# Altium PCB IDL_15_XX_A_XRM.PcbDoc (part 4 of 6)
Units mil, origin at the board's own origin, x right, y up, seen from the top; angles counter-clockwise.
Board outline 6653.34 x 6653.34 mil, 6 copper layers (Top Layer - SIG1, Layer 2 - GND1, Layer 3 - PWR, Layer 4 - PWR, Layer 5 - GND2, Bottom Layer - SIG4), stack 59.843 mil thick; 613 components, 324 nets, 1673 pads, 2316 vias.
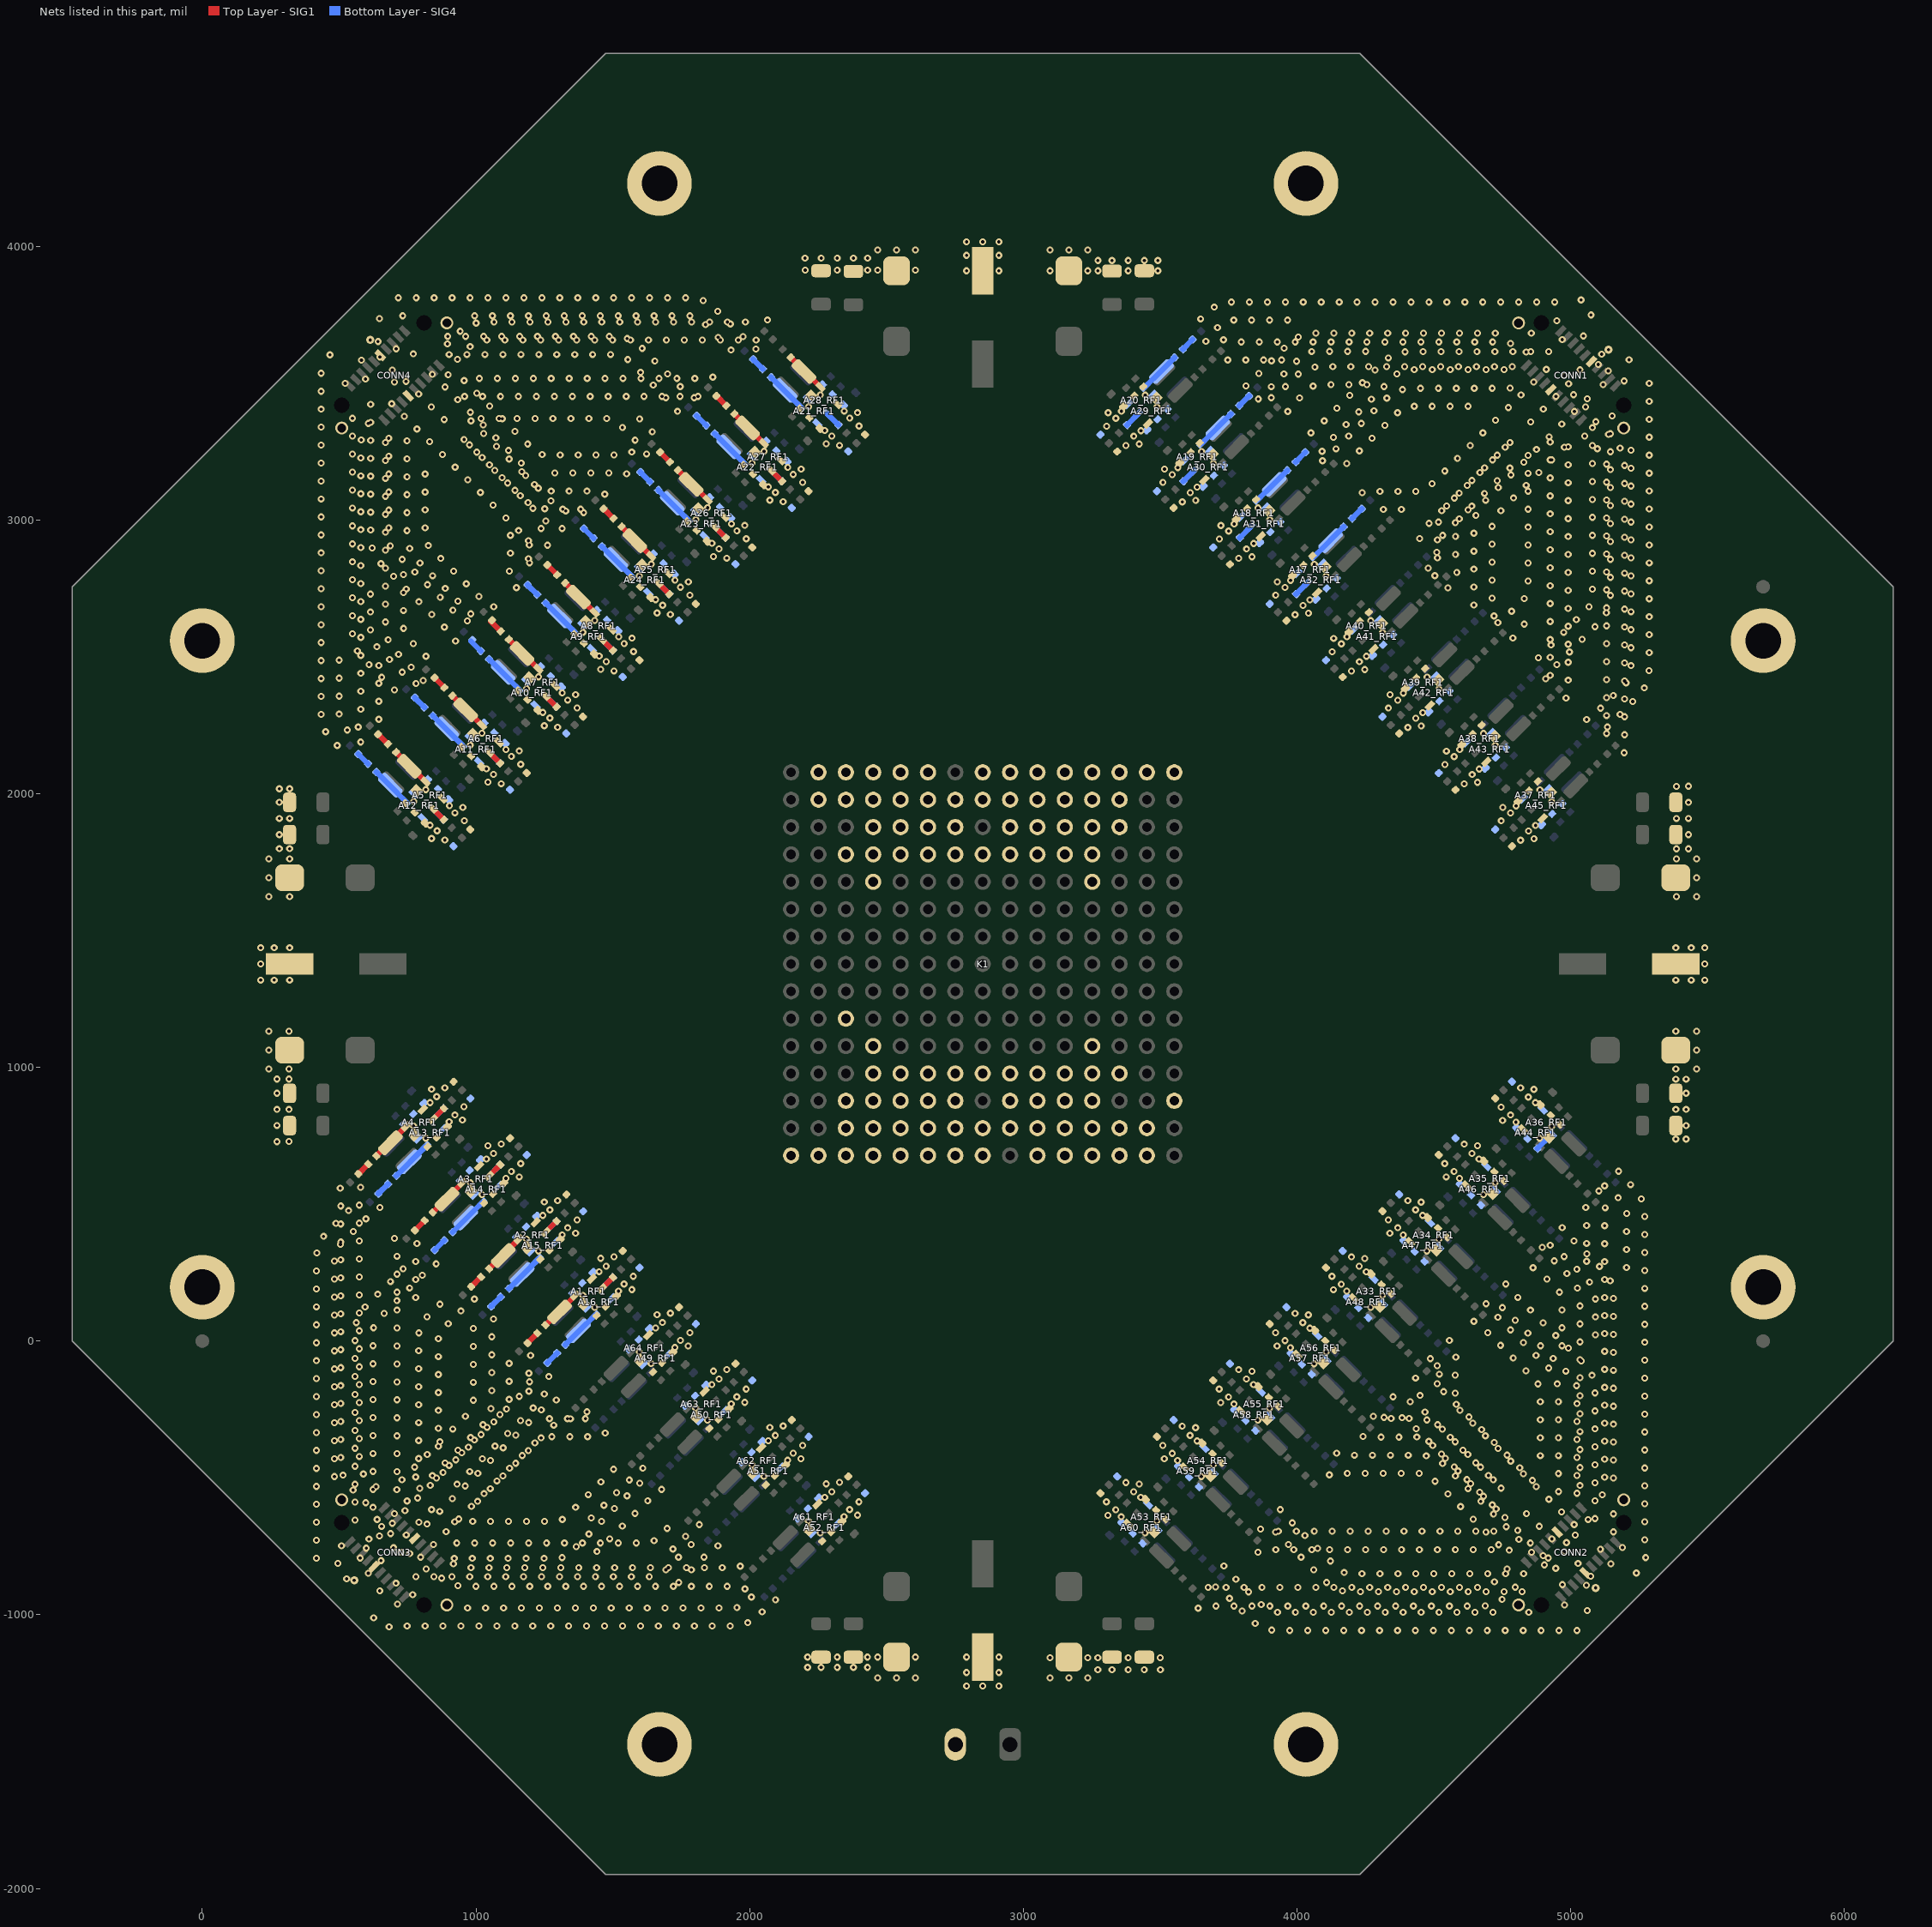
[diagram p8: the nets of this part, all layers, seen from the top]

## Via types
v1: diameter 25.59, hole 11.81, Layer 5 - GND2 to Bottom Layer - SIG4, tented both sides, 1069 vias
v2: diameter 25.59, hole 11.81, Top Layer - SIG1 to Layer 2 - GND1, tented both sides, 851 vias
v3: diameter 25.59, hole 11.81, Top Layer - SIG1 to Bottom Layer - SIG4, tented both sides, 384 vias
v4: diameter 29.53, hole 11.81, Top Layer - SIG1 to Bottom Layer - SIG4, tented both sides, 8 vias
v5: diameter 29.53, hole 11.81, Top Layer - SIG1 to Layer 2 - GND1, tented both sides, 4 vias

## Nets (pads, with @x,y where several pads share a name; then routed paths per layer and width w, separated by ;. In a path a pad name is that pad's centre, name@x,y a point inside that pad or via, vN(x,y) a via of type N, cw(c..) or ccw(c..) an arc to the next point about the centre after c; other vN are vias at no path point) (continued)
GND: A1_C1.2 A1_C2.2 A1_C3.2 A1_RF1.2 A1_RF1.4 A1_Rin_1.1 A2_C1.2 A2_C2.2 A2_C3.2 A2_RF1.2 A2_RF1.4 A2_Rin_1.1 A3_C1.2 A3_C2.2 A3_C3.2 A3_RF1.2 A3_RF1.4 A3_Rin_1.1 A4_C1.2 A4_C2.2 A4_C3.2 A4_RF1.2 A4_RF1.4 A4_Rin_1.1 A5_C1.2 A5_C2.2 A5_C3.2 A5_RF1.2 A5_RF1.4 A5_Rin_1.1 A6_C1.2 A6_C2.2 A6_C3.2 A6_RF1.2 A6_RF1.4 A6_Rin_1.1 A7_C1.2 A7_C2.2 A7_C3.2 A7_RF1.2 A7_RF1.4 A7_Rin_1.1 A8_C1.2 A8_C2.2 A8_C3.2 A8_RF1.2 A8_RF1.4 A8_Rin_1.1 A9_C1.2 A9_C2.2 A9_C3.2 A9_RF1.2 A9_RF1.4 A9_Rin_1.1 A10_C1.2 A10_C2.2 A10_C3.2 A10_RF1.2 A10_RF1.4 A10_Rin_1.1 A11_C1.2 A11_C2.2 A11_C3.2 A11_RF1.2 A11_RF1.4 A11_Rin_1.1 A12_C1.2 A12_C2.2 A12_C3.2 A12_RF1.2 A12_RF1.4 A12_Rin_1.1 A13_C1.2 A13_C2.2 A13_C3.2 A13_RF1.2 A13_RF1.4 A13_Rin_1.1 A14_C1.2 A14_C2.2 A14_C3.2 A14_RF1.2 A14_RF1.4 A14_Rin_1.1 A15_C1.2 A15_C2.2 A15_C3.2 A15_RF1.2 A15_RF1.4 A15_Rin_1.1 A16_C1.2 A16_C2.2 A16_C3.2 A16_RF1.2 A16_RF1.4 A16_Rin_1.1 A17_C1.2 A17_C2.2 A17_C3.2 A17_RF1.2 A17_RF1.4 A17_Rin_1.1 A18_C1.2 A18_C2.2 A18_C3.2 A18_RF1.2 A18_RF1.4 A18_Rin_1.1 A19_C1.2 A19_C2.2 A19_C3.2 A19_RF1.2 A19_RF1.4 A19_Rin_1.1 A20_C1.2 A20_C2.2 A20_C3.2 A20_RF1.2 A20_RF1.4 A20_Rin_1.1 A21_C1.2 A21_C2.2 A21_C3.2 A21_RF1.2 A21_RF1.4 A21_Rin_1.1 A22_C1.2 A22_C2.2 A22_C3.2 A22_RF1.2 A22_RF1.4 A22_Rin_1.1 A23_C1.2 A23_C2.2 A23_C3.2 A23_RF1.2 A23_RF1.4 A23_Rin_1.1 A24_C1.2 A24_C2.2 A24_C3.2 A24_RF1.2 A24_RF1.4 A24_Rin_1.1 A25_C1.2 A25_C2.2 A25_C3.2 A25_RF1.2 A25_RF1.4 A25_Rin_1.1 A26_C1.2 A26_C2.2 A26_C3.2 A26_RF1.2 A26_RF1.4 A26_Rin_1.1 A27_C1.2 A27_C2.2 A27_C3.2 A27_RF1.2 A27_RF1.4 A27_Rin_1.1 A28_C1.2 A28_C2.2 A28_C3.2 A28_RF1.2 A28_RF1.4 A28_Rin_1.1 A29_C1.2 A29_C2.2 A29_C3.2 A29_RF1.2 A29_RF1.4 A29_Rin_1.1 A30_C1.2 A30_C2.2 A30_C3.2 A30_RF1.2 A30_RF1.4 A30_Rin_1.1 A31_C1.2 A31_C2.2 A31_C3.2 A31_RF1.2 A31_RF1.4 A31_Rin_1.1 A32_C1.2 A32_C2.2 A32_C3.2 A32_RF1.2 A32_RF1.4 A32_Rin_1.1 A33_C1.2 A33_C2.2 A33_C3.2 A33_RF1.2 A33_RF1.4 A33_Rin_1.1 A34_C1.2 A34_C2.2 A34_C3.2 A34_RF1.2 A34_RF1.4 A34_Rin_1.1 A35_C1.2 A35_C2.2 A35_C3.2 A35_RF1.2 A35_RF1.4 A35_Rin_1.1 A36_C1.2 A36_C2.2 A36_C3.2 A36_RF1.2 A36_RF1.4 A36_Rin_1.1 A37_C1.2 A37_C2.2 A37_C3.2 A37_RF1.2 A37_RF1.4 A37_Rin_1.1 A38_C1.2 A38_C2.2 A38_C3.2 A38_RF1.2 A38_RF1.4 A38_Rin_1.1 A39_C1.2 A39_C2.2 A39_C3.2 A39_RF1.2 A39_RF1.4 A39_Rin_1.1 A40_C1.2 A40_C2.2 A40_C3.2 A40_RF1.2 A40_RF1.4 A40_Rin_1.1 A41_C1.2 A41_C2.2 A41_C3.2 A41_RF1.2 A41_RF1.4 A41_Rin_1.1 A42_C1.2 A42_C2.2 A42_C3.2 A42_RF1.2 A42_RF1.4 A42_Rin_1.1 A43_C1.2 A43_C2.2 A43_C3.2 A43_RF1.2 A43_RF1.4 A43_Rin_1.1 A44_C1.2 A44_C2.2 A44_C3.2 A44_RF1.2 A44_RF1.4 A44_Rin_1.1 A45_C1.2 A45_C2.2 A45_C3.2 A45_RF1.2 A45_RF1.4 A45_Rin_1.1 A46_C1.2 A46_C2.2 A46_C3.2 A46_RF1.2 A46_RF1.4 A46_Rin_1.1 A47_C1.2 A47_C2.2 A47_C3.2 A47_RF1.2 A47_RF1.4 A47_Rin_1.1 A48_C1.2 A48_C2.2 A48_C3.2 A48_RF1.2 A48_RF1.4 A48_Rin_1.1 A49_C1.2 A49_C2.2 A49_C3.2 A49_RF1.2 A49_RF1.4 A49_Rin_1.1 A50_C1.2 A50_C2.2 A50_C3.2 A50_RF1.2 A50_RF1.4 A50_Rin_1.1 A51_C1.2 A51_C2.2 A51_C3.2 A51_RF1.2 A51_RF1.4 A51_Rin_1.1 A52_C1.2 A52_C2.2 A52_C3.2 A52_RF1.2 A52_RF1.4 A52_Rin_1.1 A53_C1.2 A53_C2.2 A53_C3.2 A53_RF1.2 A53_RF1.4 A53_Rin_1.1 A54_C1.2 A54_C2.2 A54_C3.2 A54_RF1.2 A54_RF1.4 A54_Rin_1.1 A55_C1.2 A55_C2.2 A55_C3.2 A55_RF1.2 A55_RF1.4 A55_Rin_1.1 A56_C1.2 A56_C2.2 A56_C3.2 A56_RF1.2 A56_RF1.4 A56_Rin_1.1 A57_C1.2 A57_C2.2 A57_C3.2 A57_RF1.2 A57_RF1.4 A57_Rin_1.1 A58_C1.2 A58_C2.2 A58_C3.2 A58_RF1.2 A58_RF1.4 A58_Rin_1.1 A59_C1.2 A59_C2.2 A59_C3.2 A59_RF1.2 A59_RF1.4 A59_Rin_1.1 A60_C1.2 A60_C2.2 A60_C3.2 A60_RF1.2 A60_RF1.4 A60_Rin_1.1 A61_C1.2 A61_C2.2 A61_C3.2 A61_RF1.2 A61_RF1.4 A61_Rin_1.1 A62_C1.2 A62_C2.2 A62_C3.2 A62_RF1.2 A62_RF1.4 A62_Rin_1.1 A63_C1.2 A63_C2.2 A63_C3.2 A63_RF1.2 A63_RF1.4 A63_Rin_1.1 A64_C1.2 A64_C2.2 A64_C3.2 A64_RF1.2 A64_RF1.4 A64_Rin_1.1 C4.2 C5.2 C6.2 C7.2 C8.2 C9.2 C10.2 C11.2 C12.2 C14.2 C15.2 C16.2 C17.2 C18.2 C19.2 C20.2 C21.2 C22.2 C23.2 C24.2 C25.2 C26.2 C27.2 C28.2 C29.2 C30.2 C31.2 C32.2 CONN1.0@4809.35,3719.85 CONN1.0@5193.52,3335.67 CONN1.9 CONN1.12 CONN2.0@4809.35,-964.14 CONN2.0@5193.52,-579.96 CONN2.9 CONN2.12 CONN3.0@509.44,-579.96 CONN3.0@893.62,-964.14 CONN3.9 CONN3.12 CONN4.0@509.35,3335.86 CONN4.0@893.52,3720.04 CONN4.9 CONN4.12 K1.A3 K1.A15 K1.B1 K1.B2 K1.B15 K1.C1 K1.C2 K1.C4 K1.C13 K1.C14 K1.C15 K1.D1 K1.D2 K1.D3 K1.D4 K1.D5 K1.D11 K1.D12 K1.D13 K1.D14 K1.D15 K1.E1 K1.E2 K1.E3 K1.E4 K1.E12 K1.E13 K1.E14 K1.E15 K1.F1 K1.F2 K1.F3 K1.F4 K1.F12 K1.F13 K1.F14 K1.F15 K1.G2 K1.G3 K1.G4 K1.G12 K1.G13 K1.G14 K1.G15 K1.H1 K1.H2 K1.H4 K1.H12 K1.H14 K1.H15 K1.J1 K1.J2 K1.J3 K1.J4 K1.J12 K1.J13 K1.J14 K1.K1 K1.K2 K1.K3 K1.K4 K1.K12 K1.K13 K1.K14 K1.K15 K1.L1 K1.L2 K1.L3 K1.L4 K1.L12 K1.L13 K1.L14 K1.L15 K1.M1 K1.M2 K1.M3 K1.M4 K1.M5 K1.M11 K1.M12 K1.M13 K1.M14 K1.M15 K1.N1 K1.N2 K1.N3 K1.N6 K1.N12 K1.N14 K1.N15 K1.P1 K1.P14 K1.P15 K1.R1 K2.2 pad.M3 | length 70
  Bottom Layer - SIG4 w20: A36_C1.2@4877.76,703.14 A36_RF1.2@4927.29,752.67
  other v1: 3973.3,-1057.08 4038.89,-1057.08 4104.48,-1057.08 4170.07,-1057.08 4235.66,-1057.08 4301.25,-1057.08 4366.84,-1057.08 4432.43,-1057.08 4498.02,-1057.08 4563.62,-1057.08 4629.21,-1057.08 4694.8,-1057.08 4760.39,-1057.08 4825.98,-1057.08 4891.57,-1057.08 4957.16,-1057.08 5022.75,-1057.08 3907.72,-1055.67 682.75,-1044.28 748.25,-1040.85 813.84,-1040.85 879.43,-1040.85 945.02,-1040.85 1010.61,-1040.85 1076.2,-1040.85 1141.79,-1040.85 1207.38,-1040.85 1272.97,-1040.85 1338.56,-1040.85 1404.15,-1040.85 1469.74,-1040.85 1535.34,-1040.85 1600.93,-1040.85 1666.52,-1040.85 1732.11,-1040.85 1797.7,-1040.85 1863.29,-1040.85 1928.88,-1040.85 3846.86,-1031.23 1993.34,-1028.73 626.36,-1010.78 3928.39,-991.13 3993.98,-991.13 4059.57,-991.13 4125.16,-991.13 4190.75,-991.13 4256.34,-991.13 4321.93,-991.13 4387.52,-991.13 4453.11,-991.13 4518.7,-991.13 4584.29,-991.13 4649.88,-991.13 4715.47,-991.13 4846.66,-991.13 2045.62,-989.13 3799.17,-986.2 5060.1,-984.51 969.44,-974.89 1035.03,-974.89 1100.62,-974.89 1166.21,-974.89 1231.8,-974.89 1297.39,-974.89 1362.99,-974.89 1428.58,-974.89 1494.17,-974.89 1559.76,-974.89 1625.35,-974.89 1690.94,-974.89 1756.53,-974.89 1822.12,-974.89 1887.71,-974.89 1953.29,-973.47 4977.43,-964.48 3869.17,-962.92 712.78,-961.37 2094.31,-945.18 3752.79,-939.82 2006.43,-935.03 768.45,-926.68 3822.79,-916.54 4231.68,-915.76 4297.27,-915.76 4362.86,-915.76 4428.45,-915.76 4494.04,-915.76 4559.63,-915.76 4625.23,-915.76 4690.82,-915.76 4756.41,-915.76 4822,-915.76 648.38,-912.19 4166.2,-911.96 3702.03,-898.28 5056.85,-892.18 4969.55,-889.64 707.9,-884.63 1740.74,-881.99 4107.88,-881.95 3776.41,-870.16 527.61,-868.85 780.42,-860.72 846.02,-860.72 911.61,-860.72 977.2,-860.72 1042.79,-860.72 1108.38,-860.72 1173.97,-860.72 1239.56,-860.72 1305.15,-860.72 1370.74,-860.72 1436.33,-860.72 1501.92,-860.72 1567.51,-860.72 1633.1,-860.72 5073.17,-858.8 4237.23,-849.8 4302.82,-849.8 4368.41,-849.8 4434,-849.8 4499.59,-849.8 4565.18,-849.8 4630.77,-849.8 4696.37,-849.8 4761.96,-849.8 4827.55,-849.8 606.88,-848.51 5239.77,-847.3 4171.78,-845.48 1693.74,-835.71 1787.12,-835.61 4061.03,-836.04 4945.23,-830.29 3732.5,-821.44 4903.24,-817.38 5146.24,-813.68 5026.59,-812.62 495.04,-811.92 4121.56,-803.29 653.04,-801.91 920.83,-793.79 986.42,-793.79 1052.01,-793.79 1117.6,-793.79 1183.19,-793.79 1248.78,-793.79 416.88,-793.08 577.18,-792.64 1314.32,-791.17 5273.81,-791.24 1740.12,-789.33 4014.65,-789.66 797.87,-789.18 1833.5,-789.23 4898.85,-783.91 4856.86,-771 1441.98,-768.74 4977.43,-769.2 5108.43,-760.09 599.18,-756.48 4075.18,-756.91 698.53,-754.66 5188.66,-753.9 1366.29,-751.15 508.63,-747.75 1884.27,-747.7 3968.27,-743.28 4736.48,-743.9 844.25,-742.8 1786.5,-742.95 4852.47,-737.53 416.88,-727.49 5269.85,-725.76 4810.48,-724.62 608.95,-723.3 1488.36,-722.36 4931.05,-722.82 647.64,-712.27 4028.8,-710.53 744.91,-708.28 1412.67,-704.77 3444.69,-700.99 3921.26,-697.54 4690.1,-697.52 890.63,-696.42 5156.07,-696.98 4806.09,-691.15 4764.1,-678.24 655.33,-676.92 4884.67,-676.44 1534.74,-675.98 5012.65,-670.57 694.02,-665.89 3982.42,-664.15 416.88,-661.9 791.29,-661.9 5269.85,-660.17 1459.05,-658.39 2214.73,-657.45 558.2,-654.03 4643.72,-651.14 937.01,-650.04 5088.75,-648.61 4759.71,-644.77 2344.88,-641.45 2393.6,-635.88 4717.72,-631.86 5155.68,-631.39 701.71,-630.54 1581.12,-629.6 4838.29,-630.06 4966.27,-624.19 740.4,-619.51 837.67,-615.52 3337.51,-616.09 3938.51,-615.43 1505.43,-612.01 624.16,-607.41 4597.34,-604.76 983.39,-603.66 4713.33,-598.39 416.88,-596.31 5269.85,-594.58 558.2,-588.44 2399.17,-587.16 4671.34,-585.48 748.09,-584.16 1627.5,-583.22 5088.75,-583.02 4919.89,-577.81 786.78,-573.13 3428.68,-570.85 1551.81,-565.63 4550.96,-558.38 1029.77,-557.28 5022.79,-556.17 4666.95,-552.01 2299.64,-550.28 624.16,-541.81 1678.26,-541.69 4624.96,-539.1 794.47,-537.78 4745.53,-537.31 4873.51,-531.43 416.88,-530.71 5269.85,-528.99 833.16,-526.75 558.2,-522.85 930.43,-522.76 3423.11,-522.13 1598.19,-519.25 5088.75,-517.43 3374.39,-516.56 4504.58,-512 1076.15,-510.9 729.28,-506.84 4620.57,-505.63 5155.68,-500.21 482.84,-495.06 3650.69,-494.99 4578.58,-492.72 840.85,-491.4 4699.15,-490.93 5022.79,-490.58 4118.14,-488.46 4827.13,-485.05 4183.48,-482.81 4249.08,-482.81 4314.67,-482.81 4380.26,-482.81 4445.85,-482.81 879.54,-480.37 976.81,-476.38 624.16,-476.22 416.88,-465.12 1122.53,-464.52 5269.85,-463.4 775.66,-460.46 4574.2,-459.25 558.2,-457.26 2008.73,-451.45 5088.75,-451.84 4531.43,-447.12 887.23,-445.02 4652.77,-444.55 4780.75,-438.67 2138.87,-435.44 5155.68,-434.62 925.92,-433.99 482.84,-429.47 1023.19,-430 2187.59,-429.87 5022.79,-424.99 4472,-419.39 1168.91,-418.14 4209.68,-416.85 4275.27,-416.85 4340.86,-416.85 4406.45,-416.85 822.04,-414.08 4527.82,-412.87 624.16,-410.63 3543.51,-410.08 4144.51,-409.42 416.88,-399.53 933.61,-398.64 4606.39,-398.17 5269.85,-397.81 4734.37,-392.29 558.2,-391.67 972.3,-387.62 5088.75,-386.25 1069.57,-383.62 2193.16,-381.15 1215.29,-371.76 5155.68,-369.03 868.42,-367.71 4481.44,-366.49 3634.69,-364.84 482.84,-363.88 5022.79,-359.4 979.99,-352.26 4560.01,-351.79 1276.85,-349.15 1342.45,-349.15 1408.04,-349.15 4687.99,-345.91 624.16,-345.04 2093.63,-344.27 1018.68,-341.24 1115.95,-337.24 1472.22,-335.65 416.88,-333.94 5269.85,-332.22 558.2,-326.08 914.79,-321.33 5088.75,-320.66 4435.06,-320.11 3629.12,-316.12 3580.4,-310.55 1025.75,-305.27 4513.63,-305.41 5155.68,-303.44 4641.61,-299.53 482.84,-298.29 1065.05,-294.86 5022.79,-293.81 1162.33,-290.87 3856.7,-288.98 1268.46,-283.19 1334.05,-283.19 1399.64,-283.19 624.16,-279.45 4383.22,-279.92 4317.65,-278.6 961.17,-274.95 416.88,-268.35 5269.85,-266.63 558.2,-260.49 4467.25,-259.03 5088.75,-255.07 4595.29,-253.09 1111.43,-248.48 1054.78,-246.46 1802.72,-245.44 1208.71,-244.49 5155.68,-237.85 482.84,-232.7 1932.86,-229.43 5022.79,-228.22 1981.58,-223.86 4413.69,-221.17 990.14,-216.1 624.16,-213.86 3749.52,-204.07 4350.56,-203.38 416.88,-202.76 1157.81,-202.1 5269.85,-201.04 558.2,-194.9 1249.35,-193 4578.15,-189.78 5088.75,-189.48 1058.12,-180.95 1987.15,-175.15 5155.68,-172.26 482.84,-167.1 5021.07,-162.65 3840.69,-158.83 4512.19,-155.65 990.14,-150.51 624.16,-148.27 1195.75,-148.59 1887.63,-138.26 416.88,-137.17 5269.85,-135.45 558.2,-129.31 1266.18,-129.61 5077.19,-124.91 4578.15,-124.19 1058.12,-115.36 3835.13,-110.11 4982.25,-109.78 5155.68,-106.67 3786.41,-104.55 482.84,-101.51 4512.19,-90.06 990.14,-84.92 624.16,-82.68 4062.74,-82.94 5038.04,-72.29 416.88,-71.58 5269.85,-69.86 558.2,-63.72 4935.87,-63.4 4579.97,-58.63 1058.12,-49.77 5155.68,-41.08 1596.68,-39.4 482.84,-35.92 4991.66,-25.91 1726.82,-23.39 990.14,-19.33 1775.54,-17.82 624.16,-17.09 4889.49,-17.02 416.88,-5.99 5269.85,-4.27 558.2,1.87 3955.56,1.97 4556.6,2.66 1058.12,15.82 4945.28,20.47 5089.72,22.59 5155.68,24.51 482.84,29.67 4843.11,29.35 1781.11,30.89 990.14,46.26 4046.74,47.21 625.84,48.48 416.88,59.6 5269.85,61.32 563.08,67.28 4898.9,66.85 1681.59,67.78 4796.73,75.73 1064.24,81.12 5089.72,88.18 5155.68,90.1 482.84,95.26 4041.17,95.93 664.62,101.38 3992.45,101.49 4852.52,113.23 4750.36,122.11 4268.78,123.1 594.91,124.63 416.88,125.19 5269.85,126.91 711,147.76 5089.72,153.77 5155.68,155.7 4806.14,159.61 482.84,160.85 1390.64,166.64 641.13,171.17 1520.78,182.65 1569.5,188.22 416.88,190.78 5269.85,192.5 757.38,194.14 4161.6,208.01 4762.6,208.67 5068.61,215.87 687.51,217.55 5144.09,220.25 482.84,226.44 1575.07,236.94 803.76,240.52 4252.78,253.25 416.88,256.37 5269.85,258.09 5022.23,262.25 733.89,263.93 5203.89,269.19 5104.91,272.86 1475.54,273.82 854.52,282.05 482.84,292.03 4247.21,301.97 4198.49,307.54 4975.85,308.63 5058.53,319.24 418.35,321.95 5269.85,323.68 4474.79,329.11 5203.89,334.78 4924.9,349.93 504.99,353.77 5012.15,365.62 1184.99,372.29 443.09,382.69 1315.13,388.3 5269.85,389.28 1363.85,393.87 551.37,400.15 5203.89,400.37 4367.61,414.02 4968.61,414.67 488.23,430.28 1369.42,442.59 597.75,446.53 5269.85,454.87 4458.78,459.26 5204.04,465.96 534.61,476.66 1269.89,479.47 648.52,488.06 4453.22,507.98 4404.5,513.54 5257.75,519.33 5172.84,523.66 4680.8,535.12 5123.94,567.38 5218.16,571.62 978.98,578.3 1109.12,594.31 1157.84,599.88 4573.62,620.03 5174.62,620.68 1163.41,648.59 4664.79,665.26 1063.89,685.48 4659.22,713.98 4610.51,719.55 4886.81,741.13 771.56,785.72 901.7,801.73 950.42,807.3 4779.63,826.03 955.99,856.02 4870.8,871.27 856.46,892.9 4865.23,919.99 4816.51,925.56 886.35,1830.35 837.64,1835.92 4845.44,1863.86 832.07,1884.63 4745.92,1900.75 923.24,1929.87 4751.48,1949.47 4800.2,1955.03 4930.35,1971.04 816.06,2014.78 1092.36,2036.36 1043.64,2041.92 4639.43,2069.87 1038.07,2090.64 4539.91,2106.76 1129.25,2135.88 4545.48,2155.47 4594.19,2161.04 493.01,2175.91 4724.34,2177.05 578.83,2188.76 1022.07,2220.79 450.78,2226.09 529.83,2232.37 1298.37,2242.36 5133.68,2243.66 1249.65,2247.93 5057.81,2271.22 4433.42,2275.88 434.19,2289.55 5180.06,2290.04 500.11,2290.84 1244.08,2296.65 5108.99,2312.24 4333.9,2312.76 5226.44,2336.41 1335.25,2341.89 434.15,2355.14 500.11,2356.43 5155.37,2358.62 4339.47,2361.48 4388.19,2367.05 701.97,2378.97 4518.33,2383.06 5268.97,2386.35 780.91,2402.25 5201.85,2404.89 434.15,2420.73 4907.93,2419.88 500.11,2422.02 655.59,2425.35 1228.08,2426.8 730.28,2443.94 1504.38,2448.37 5286.22,2449.63 1455.66,2453.94 5220.48,2467.78 609.21,2471.73 4949.02,2471.01 4227.42,2481.88 434.15,2486.32 500.11,2487.61 683.9,2490.32 4881.32,2496.59 1450.09,2502.66 5286.44,2515.22 4995.4,2517.39 4127.89,2518.77 566.46,2521.48 5220.48,2533.37 637.52,2536.7 4927.7,2542.97 1541.26,2547.89 434.15,2551.92 925.41,2557.18 5041.78,2563.77 4133.46,2567.49 4182.18,2573.06 5286.44,2580.81 548.56,2584.58 4312.32,2589.06 4974.08,2589.35 614.29,2598.04 5220.48,2598.97 884.51,2608.45 5088.16,2610.15 434.15,2617.51 968.27,2631.54 1434.08,2632.8 5020.46,2635.73 5286.44,2646.4 4719.75,2649.37 548.33,2650.17 1710.42,2654.41 838.13,2654.83 1661.7,2659.98 5129.82,2660.8 614.29,2663.63 5220.48,2664.56 915.6,2670.63 5066.31,2682.63 434.15,2683.1 4021.38,2687.93 4646.21,2689.15 791.75,2701.21 1656.13,2708.7 5286.44,2711.99 4712.17,2714.52 548.33,2715.76 869.22,2717.01 5145.12,2724.59 3921.85,2724.81 614.29,2729.22 5220.48,2730.15 745.37,2747.59 5079.16,2746.95 434.15,2748.69 1147.99,2752.79 1747.3,2753.94 4646.21,2754.74 822.84,2763.39 3927.42,2773.53 5286.44,2777.58 3976.14,2779.1 4712.17,2780.11 548.33,2781.35 5145.12,2790.18 698.99,2793.97 4106.28,2795.11 5220.48,2795.74 776.46,2809.77 5079.16,2812.54 1121.69,2812.88 434.15,2814.28 4646.21,2820.33 4479.46,2824.15 1640.12,2838.84 652.76,2840.5 5286.44,2843.18 4712.17,2845.7 548.33,2846.94 730.08,2856.15 5145.12,2855.77 1191.81,2858.47 1916.42,2860.42 5220.48,2861.33 1867.71,2865.99 1125.85,2878.33 5079.16,2878.13 434.15,2879.87 4510.71,2881.82 4646.21,2885.92 3815.37,2893.93 620.4,2897.55 686.88,2905.5 5286.44,2908.77 4712.17,2911.29 548.33,2912.53 1862.14,2914.7 5145.12,2921.36 1191.81,2924.06 5220.48,2926.92 3715.84,2930.82 4447.4,2931.79 5079.16,2943.72 1125.85,2943.92 4531.94,2943.88 434.15,2945.46 4646.21,2951.51 1953.31,2959.94 615.26,2962.94 1314.63,2968.6 681.22,2970.85 5286.44,2974.36 4712.17,2976.88 548.33,2978.12 3721.41,2979.54 3770.13,2985.11 4482.18,2987.4 5145.12,2986.95 4578.32,2990.26 5220.48,2992.51 1255.33,2996.62 3900.28,3001.11 1109.09,3007.34 5079.16,3009.31 434.15,3011.05 4653.48,3016.7 1393.46,3026.59 615.26,3028.53 1328.16,3032.72 4528.56,3033.78 4744.42,3034 681.22,3036.44 4624.7,3036.64 4315.45,3038.54 4381.04,3038.54 5286.44,3039.95 1208.22,3042.26 548.33,3043.71 1846.13,3044.85 5145.12,3052.54 1062.81,3053.81 5220.48,3058.1 2122.43,3066.43 1274.02,3069.75 2073.71,3071.99 4688.99,3071.85 5079.16,3074.9 434.15,3076.64 4574.94,3080.16 4790.8,3080.38 1161.84,3088.64 615.26,3094.12 4237.48,3099.23 1016.43,3100.19 3609.36,3099.94 681.22,3102.03 4302.86,3104.5 4368.45,3104.5 4434.04,3104.5 5286.44,3105.54 548.33,3109.3 1227.64,3116.12 4735.37,3118.23 5145.12,3118.13 2068.15,3120.71 5220.48,3123.69 4621.32,3126.54 4837.18,3126.76 4493.38,3132.46 1115.46,3135.02 3509.84,3136.83 5079.16,3140.5 434.15,3142.23 970.05,3146.57 615.26,3159.71 1181.26,3162.5 4781.75,3164.61 2159.32,3165.95 681.22,3167.62 1550.51,3168.82 1288.2,3171.56 1353.79,3171.56 1419.38,3171.56 1484.97,3171.56 5286.44,3171.13 4667.69,3172.92 4883.56,3173.14 548.33,3174.89 4539.76,3178.84 1069.08,3181.4 5145.12,3183.72 3515.4,3185.55 5220.48,3189.28 3564.12,3191.11 923.67,3192.95 5079.16,3206.09 3694.27,3207.12 434.15,3207.82 1165.34,3207.97 4828.13,3210.99 4714.07,3219.3 4929.94,3219.52 615.26,3225.3 4586.14,3225.22 1022.7,3227.78 681.22,3233.21 5286.44,3236.72 1307.54,3237.51 1373.13,3237.51 1438.72,3237.51 1504.31,3237.51 877.29,3239.33 1241.97,3238.92 548.33,3240.48 1569.07,3247.94 5145.12,3249.31 4091.62,3250.72 2052.14,3250.86 1118.73,3254.12 5220.48,3254.87 4874.51,3257.37 4760.45,3265.68 4976.32,3265.9 4632.52,3271.6 5079.16,3271.68 2328.44,3272.43 434.15,3273.41 976.32,3274.16 1188.8,3277.33 2279.72,3278 830.91,3285.71 615.26,3290.9 681.22,3298.8 1072.35,3300.5 4132.53,3302 5286.44,3302.31 4920.89,3303.75 548.33,3306.07 3403.35,3305.95 5145.12,3314.9 4050.42,3318.38 4678.9,3317.98 1142.42,3323.71 2274.15,3326.72 784.53,3332.09 5079.16,3337.27 434.15,3339 3303.83,3342.83 1025.97,3346.88 4178.91,3348.38 4967.27,3350.13 615.26,3356.49 4853.21,3358.44 4099.33,3362.08 4725.27,3364.36 883.56,3366.92 5286.44,3367.9 1096.04,3370.09 548.33,3371.66 2365.33,3371.96 738.15,3378.47 5151.42,3380.19 3309.4,3391.55 979.59,3393.26 4225.29,3394.76 5013.65,3396.51 1736.54,3396.84 3358.12,3397.12 434.15,3404.59 4899.59,3404.82 4145.71,3408.46 4771.65,3410.74 837.18,3413.3 3488.26,3413.13 1049.66,3416.47 615.26,3422.08 691.77,3424.85 5286.44,3433.49 933.21,3439.64 3858.29,3441.66 4271.67,3441.13 5060.03,3442.89 1693.82,3446.61 1797.32,3446.43 4945.97,3451.2 4192.09,3454.84 2258.15,3456.87 4818.03,3457.12 790.8,3459.68 1003.28,3462.85 434.15,3470.18 886.83,3486.02 1746.2,3487.52 3905.6,3487.09 4318.04,3487.51 3813.2,3489.3 1647.44,3492.99 5118.39,3494.8 4992.35,3497.58 521.9,3499.45 5286.44,3499.08 4238.47,3501.22 4864.41,3503.5 744.42,3506.06 5195.14,3507.92 956.9,3509.23 596.19,3514.6 840.45,3532.4 3951.98,3533.47 4364.66,3533.66 1699.82,3533.9 3860.24,3535.01 434.15,3535.77 1601.07,3539.37 5137.04,3544.41 4284.85,3547.6 694.04,3548.05 5033.78,3548.43 4428.4,3549.14 4493.99,3549.14 4559.58,3549.14 4625.17,3549.14 4690.76,3549.14 4756.35,3549.14 4910.79,3549.88 5100.54,3567.65 1653.44,3580.28 3998.36,3579.84 3906.62,3581.39 581.76,3583.29 5213.05,3585.57 1554.8,3585.86 4333.12,3592.01 648.65,3595.4 466.49,3603.3 901.6,3604.51 967.19,3604.51 1032.78,3604.51 1098.37,3604.51 1163.96,3604.51 1229.55,3604.51 1295.14,3604.51 1360.73,3604.51 1426.32,3604.51 1491.91,3604.51 5112.83,3605.37 771.25,3606.72 4394.89,3614.07 4053.43,3615.47 4460.47,3615.1 4526.06,3615.1 4591.66,3615.1 4657.25,3615.1 4722.84,3615.1 4788.43,3615.1 4854.02,3615.1 4919.61,3615.1 4119.02,3616.07 4184.61,3616.07 4250.2,3616.07 1931.62,3620.84 2023.03,3624.1 708.35,3625.34 1607.06,3626.66 3953,3627.77 642.06,3652.04 3666.63,3652.43 4968.74,3658.56 1552.24,3662.68 1885.24,3667.21 4004.41,3668.5 896.8,3670.47 962.39,3670.47 1027.98,3670.47 1093.57,3670.47 1159.16,3670.47 1224.75,3670.47 1290.34,3670.47 1355.94,3670.47 1421.53,3670.47 1487.12,3670.47 1975.95,3669.78 5046.01,3672.18 4068.59,3682.03 4134.18,3682.03 4199.77,3682.03 4265.37,3682.03 4330.96,3682.03 4396.55,3682.03 4462.14,3682.03 4527.73,3682.03 4593.32,3682.03 4658.91,3682.03 4724.5,3682.03 4855.68,3682.03 3709,3702.5 1838.86,3713.59 1929.58,3716.16 4949.02,3727.92 3768.43,3730.24 3834.02,3730.24 3899.61,3730.24 3965.2,3730.24 3647.74,3734.52 647.59,3736 732.28,3745.83 994.64,3745.83 1060.23,3745.83 1125.82,3745.83 1191.42,3745.83 1257.01,3745.83 1322.6,3745.83 1388.19,3745.83 1453.78,3745.83 1519.37,3745.83 1584.96,3745.83 1650.55,3745.83 1716.14,3745.83 1781.73,3745.82 5073.97,3748.89 1883.2,3762.54 3697.31,3777.48 3760.28,3795.83 3825.87,3796.2 3891.46,3796.2 3957.05,3796.2 4022.64,3796.2 4088.23,3796.2 4153.82,3796.2 4219.41,3796.2 4285,3796.2 4350.59,3796.2 4416.18,3796.2 4481.77,3796.2 4547.36,3796.2 4612.95,3796.2 4678.54,3796.2 4744.13,3796.2 4809.73,3796.2 4875.32,3796.2 4940.91,3796.2 1830.09,3801.03 5037.7,3803.54 715.94,3811.79 781.53,3811.79 847.12,3811.79 912.71,3811.79 978.3,3811.79 1043.89,3811.79 1109.48,3811.79 1175.07,3811.79 1240.66,3811.79 1306.25,3811.79 1371.85,3811.79 1437.44,3811.79 1503.03,3811.79 1568.62,3811.79 1634.21,3811.79 1699.8,3811.79 1765.39,3811.79
  other v2: 3638.66,-975.84 3703.8,-968.22 3769.39,-968.22 3834.98,-968.22 3900.57,-968.22 3966.16,-968.22 4031.75,-968.22 4097.35,-968.22 4162.94,-968.22 4228.53,-968.22 4294.12,-968.22 4359.71,-968.22 4425.3,-968.22 4490.89,-968.22 4556.48,-968.22 4622.07,-968.22 4687.65,-966.99 4749.06,-943.96 1982.95,-905.08 3675.01,-900.24 3740.6,-900.24 3806.2,-900.24 3871.79,-900.24 3937.38,-900.24 4002.97,-900.24 4068.56,-900.24 4134.15,-900.24 4199.74,-900.24 4265.33,-900.24 4330.92,-900.24 4396.51,-900.24 4462.1,-900.24 4527.69,-900.24 4593.28,-900.24 4658.87,-900.24 4797.04,-899.23 999.74,-895.84 1065.33,-895.84 1130.92,-895.84 1196.51,-895.84 1262.1,-895.84 1327.69,-895.84 1393.29,-895.84 1458.88,-895.84 1524.47,-895.84 1590.06,-895.84 1655.65,-895.84 1721.24,-895.84 1786.83,-895.84 1852.42,-895.84 1918.01,-895.84 934.19,-893.46 4720.98,-879.15 874.55,-866.16 818.24,-832.53 4767.36,-832.77 981.72,-827.86 1047.31,-827.86 1112.9,-827.86 1178.49,-827.86 1244.08,-827.86 1309.67,-827.86 1375.26,-827.86 1440.85,-827.86 1506.45,-827.86 1572.04,-827.86 1637.63,-827.86 1703.22,-827.86 1768.81,-827.86 1834.4,-827.86 1899.99,-827.86 1965.36,-822.49 917.61,-814.01 4917.75,-792.6 757.62,-775.99 725.55,-771.65 3857.47,-771.45 4775.06,-764 3922.41,-762.21 3988,-762.21 4053.59,-762.21 4119.18,-762.21 4184.77,-762.21 4250.36,-762.21 4315.95,-762.21 4381.54,-762.21 4447.13,-762.21 4512.72,-762.21 4578.32,-762.21 4643.91,-762.21 4709.5,-762.21 1719.74,-759.66 929.76,-737.88 995.35,-737.88 1060.94,-737.88 1126.53,-737.88 1192.12,-737.88 1257.71,-737.88 1323.3,-737.88 1388.89,-737.88 1454.48,-737.88 1520.07,-737.88 1585.66,-737.88 4984.25,-736.22 1650.68,-729.22 1766.12,-713.28 5016.6,-709.01 688.08,-703.26 2257.88,-700.6 3931.69,-694.23 3997.28,-694.23 4062.87,-694.23 4128.46,-694.23 4194.05,-694.23 4259.64,-694.23 4325.23,-694.23 4390.82,-694.23 4456.41,-694.23 4522,-694.23 4587.59,-694.23 4653.19,-694.23 4718.78,-694.23 3866.51,-686.88 1698.71,-684.55 1815.6,-670.23 821.03,-668.44 922.17,-659.85 987.76,-658.92 1053.35,-658.92 1118.94,-658.92 1184.53,-658.92 1250.12,-658.92 3487.84,-657.84 638.76,-651.63 1315.29,-651.51 5063.05,-651.81 1420.97,-646.41 3357.69,-641.84 3308.97,-636.27 867.41,-622.06 2365.06,-615.7 4727.29,-613.56 1363.84,-607.41 1467.35,-600.03 597.36,-590.67 3303.4,-587.55 1005.86,-585.45 913.79,-575.68 2273.89,-570.46 4680.91,-567.18 5115.27,-561.85 1410.22,-561.03 1513.73,-553.65 3402.93,-550.66 4955.5,-549.58 550.98,-544.29 710.84,-542.6 1052.24,-539.07 634.87,-532.05 960.17,-529.3 5033.84,-527.5 2279.46,-521.74 4634.53,-520.8 2328.18,-516.17 1456.6,-514.65 4859.8,-509.18 1560.11,-507.28 4716.78,-506.92 855.24,-500.6 779.73,-496.39 5123.82,-496.82 2051.88,-494.6 1098.62,-492.69 514.38,-489.86 588.75,-485.41 4954.89,-483.99 1006.55,-482.92 711.76,-477.02 4588.15,-474.42 1502.98,-468.27 1609.59,-464.23 4813.42,-462.8 5033.84,-461.91 4670.4,-460.54 901.62,-454.22 3693.84,-451.84 1145,-446.31 1052.93,-436.54 3563.7,-435.83 3514.98,-430.26 5123.82,-431.23 790.4,-429 4541.77,-428.04 505.75,-424.84 573.72,-421.56 4888.93,-418.48 4954.89,-418.4 4767.04,-416.42 4624.02,-414.16 711.76,-411.43 2159.06,-409.69 948,-407.84 1191.37,-399.93 5033.84,-396.32 1099.31,-390.16 862.41,-384.51 3509.41,-381.54 4495.39,-381.66 4720.66,-370.04 4577.64,-367.78 5123.82,-365.64 2067.88,-364.45 790.4,-363.41 994.38,-361.46 505.75,-359.25 573.72,-355.97 1237.75,-353.56 4888.93,-352.89 4954.89,-352.81 4306.52,-350.55 4372.12,-350.55 4437.71,-350.45 4240.97,-348.43 711.76,-345.84 3608.94,-344.66 1145.69,-343.78 5033.84,-330.72 4674.28,-323.66 4531.21,-321.46 862.41,-318.92 2073.45,-315.73 1040.76,-315.08 2122.17,-310.16 1284.13,-307.18 5123.82,-300.05 790.4,-297.81 1192.07,-297.4 505.75,-293.65 573.72,-290.38 1845.87,-288.59 4474.62,-288.28 4888.93,-287.3 4954.89,-287.22 1345.38,-283.71 4343.69,-282.57 4409.28,-282.57 711.76,-280.25 4627.9,-277.28 4278.56,-274.83 1087.14,-268.7 5033.84,-265.13 1405.77,-258.11 862.41,-253.33 1238.45,-251.02 3899.85,-245.83 5123.82,-234.46 790.4,-232.22 4581.52,-230.9 3769.71,-229.82 505.75,-228.06 573.72,-224.79 3720.99,-224.25 4888.93,-221.71 4954.89,-221.63 1293.57,-215.48 711.76,-214.66 1121.2,-212.65 1953.05,-203.68 5033.84,-199.54 4449.03,-198.54 862.41,-187.74 4535.15,-184.52 1193.41,-182.94 3715.42,-175.54 5123.82,-168.87 790.4,-166.63 505.75,-162.47 573.72,-159.2 1861.88,-158.44 4880.57,-156.65 4950.33,-156.2 711.76,-149.07 1121.4,-147.06 3814.94,-138.65 4433.05,-134.93 5033.84,-133.95 862.41,-122.14 4519.52,-120.82 1193.41,-117.35 1867.44,-109.73 4836.12,-108.41 1916.16,-104.16 5123.82,-103.28 790.4,-101.04 4918.98,-98.58 505.75,-96.88 573.72,-93.61 711.76,-83.48 1639.83,-82.55 1121.4,-81.47 5033.84,-68.36 4486.53,-64.13 4789.74,-62.04 862.41,-56.55 1199.73,-52.07 4872.9,-51.91 4105.89,-39.79 5123.82,-37.69 790.4,-35.45 505.75,-31.29 573.72,-28.02 3975.75,-23.78 711.76,-17.89 3927.03,-18.21 4967.88,-17.09 4743.36,-15.66 4826.52,-5.53 5033.84,-2.77 1747.01,2.36 862.41,9.04 5123.82,27.9 791.51,30.13 3921.46,30.51 4696.98,30.72 505.75,34.3 573.72,37.57 4780.14,40.85 711.76,47.71 1655.83,47.6 4967.88,48.5 5033.84,62.82 898.55,63.78 4020.98,67.39 4646.09,72.1 4733.76,87.23 821.43,88.5 5123.82,93.5 1661.4,96.32 505.75,99.89 1710.12,101.88 573.72,103.16 944.93,110.16 711.76,113.3 4967.88,114.09 1433.79,123.49 5033.84,128.41 867.81,134.88 4690.22,136.29 994.08,153.59 779.73,159.51 5123.82,159.09 505.75,165.48 4311.93,166.25 573.72,168.75 711.76,178.89 4958.16,178.96 4181.79,182.26 4133.07,187.83 5023.94,193.25 1540.97,208.4 5123.82,224.68 779.73,225.11 4913.1,226.62 505.75,231.07 573.72,234.34 4127.5,236.55 711.76,244.48 4986.15,246.86 1449.79,253.64 4862.29,268.1 4227.03,273.43 779.73,290.7 5123.82,290.27 5057.86,291.4 4939.77,293.24 505.75,296.66 573.72,299.93 1455.36,302.36 1504.08,307.92 711.76,310.07 1228.14,329.14 4896.23,342.29 784.19,356.13 5123.82,355.86 5057.86,356.99 505.75,362.25 573.72,365.52 4517.94,372.26 702.51,375 4387.8,388.27 4339.08,393.84 1335.31,414.05 5123.82,421.45 5057.86,422.58 505.75,427.84 573.72,431.11 4333.51,442.55 1244.14,459.29 4433.03,479.44 5125.61,487.01 5055.03,488.11 505.75,493.43 573.72,496.7 1249.71,508.01 1298.43,513.58 1022.13,535.15 5102.24,548.3 503.95,559 578.19,562.14 4723.95,578.27 4593.8,594.28 4545.08,599.84 1129.31,620.06 4539.52,648.56 1038.13,665.3 4639.04,685.45 1043.7,714.02 1092.42,719.58 816.12,741.16 4929.96,784.28 4799.81,800.28 4751.09,805.85 923.3,826.07 4745.52,854.57 832.13,871.3 4845.05,891.46 837.7,920.02 886.41,925.59 4816.9,1829.76 4865.62,1835.33 857.82,1864.45 4871.19,1884.05 957.34,1901.34 4780.02,1929.28 951.77,1950.05 903.06,1955.62 772.91,1971.63 4887.2,2014.19 4610.9,2035.77 4659.61,2041.33 1063.83,2070.46 4665.18,2090.05 1163.35,2107.34 4574.01,2135.29 5194.82,2149.67 1157.78,2156.06 1109.06,2161.63 978.92,2177.64 5196.56,2215.24 4681.19,2220.2 5130.6,2219.91 4404.89,2241.77 569.49,2243.59 4453.61,2247.34 644.97,2271.9 1269.83,2276.47 5196.56,2280.83 5130.6,2285.5 4459.17,2296.06 579.01,2308.49 1369.36,2313.35 644.97,2337.49 4368,2341.3 5196.56,2346.42 4982.63,2349.49 5130.6,2351.09 1363.79,2362.07 1315.07,2367.64 579.01,2374.08 1184.92,2383.65 644.97,2403.08 5196.56,2412.01 807.09,2413.49 4990.55,2414.6 5130.6,2416.68 4475.18,2426.21 4924.59,2432.12 579.01,2439.67 4198.88,2447.78 4247.6,2453.35 763.34,2462.36 644.97,2468.67 5196.56,2477.6 4990.55,2480.19 1475.84,2482.47 5130.6,2482.28 4924.59,2497.71 817,2501.99 4253.17,2502.07 579.01,2505.26 716.96,2508.74 1575.37,2519.36 5196.56,2543.19 4990.55,2545.78 4162,2547.31 770.62,2548.37 5130.6,2547.87 679.04,2562.26 4924.59,2563.3 1569.8,2568.08 4788.54,2568.72 579.01,2570.85 1521.08,2573.65 1390.93,2589.65 735.47,2603.74 5196.56,2608.78 4990.55,2611.38 5130.6,2613.46 4830.17,2619.41 4733.47,2624.69 668.99,2627.07 4924.59,2628.89 4269.17,2632.21 579.01,2636.44 3992.84,2653.82 980.66,2657.05 4041.56,2659.39 4783.99,2666.52 734.95,2669.33 5196.56,2674.37 4990.55,2676.97 5130.6,2679.05 1064.74,2683.16 1681.88,2688.51 668.99,2692.66 4924.59,2694.48 579.01,2702.03 934.28,2703.43 4047.13,2708.11 4830.37,2712.9 1010.69,2720.31 1781.41,2725.4 734.95,2734.92 5196.56,2739.96 4990.55,2742.56 5130.6,2744.64 887.9,2749.81 4551.07,2751.57 3955.95,2753.35 668.99,2758.25 4924.59,2760.07 964.31,2766.69 579.01,2767.62 1775.84,2774.12 4843.93,2777.07 1727.12,2779.69 1596.97,2795.69 841.52,2796.19 4503.32,2796.54 734.95,2800.51 5196.56,2805.55 4583.56,2808.54 4990.55,2808.15 5130.6,2810.23 917.93,2813.07 668.99,2823.84 4924.59,2825.66 579.01,2833.21 4063.13,2838.26 795.14,2842.57 4843.93,2842.66 1195.77,2843.28 871.55,2859.45 3786.83,2859.83 4512.94,2861.42 3835.55,2865.4 5196.56,2871.14 4990.55,2873.74 4578.89,2873.97 5130.6,2875.82 668.99,2889.44 4924.59,2891.25 1887.89,2894.52 757.58,2896.34 579.01,2898.8 825.8,2906.45 1261.73,2907.67 4843.93,2908.25 1194.86,2908.86 3841.12,2914.12 4512.94,2927.01 1987.41,2931.41 5196.56,2936.73 4578.89,2939.56 4990.55,2939.33 5130.6,2941.41 668.99,2955.03 4924.59,2956.84 3749.95,2959.35 747.94,2961.22 1155.39,2961.25 579.01,2964.39 1238.12,2968.87 813.9,2970.95 4843.93,2973.84 1981.85,2980.13 1933.13,2985.69 4516.64,2992.5 1802.98,3001.7 5196.56,3002.32 4592.46,3003.73 4990.55,3004.92 1109.02,3007.63 5130.6,3007 668.99,3020.62 4924.59,3022.43 747.94,3026.81 579.01,3029.98 813.9,3036.55 1316.84,3039.45 1382.43,3039.45 4843.93,3039.43 1251.26,3040.65 3857.13,3044.26 4638.4,3050.55 4546.47,3050.91 1062.64,3054.01 1189.82,3063.62 3580.83,3065.84 5196.56,3067.91 4990.55,3070.51 3629.54,3071.41 5130.6,3072.59 668.99,3086.21 4924.59,3088.03 747.94,3092.4 1470.32,3094.17 579.01,3095.58 4684.78,3096.93 4592.35,3097.78 1016.26,3100.39 2093.9,3100.53 813.9,3102.14 1274.52,3105.41 1340.11,3105.41 1405.7,3105.41 4843.93,3105.02 1141.88,3108.39 3635.11,3120.12 1213.67,3129.89 5196.56,3133.51 4990.55,3136.1 2193.42,3137.42 5130.6,3138.18 4731.16,3143.31 4638.73,3144.16 969.88,3146.77 668.99,3151.8 4924.59,3153.62 1095.5,3154.77 747.94,3157.99 579.01,3161.17 3543.94,3165.36 813.9,3167.73 4843.93,3170.62 1167.29,3176.26 2187.85,3186.13 4777.54,3189.69 4685.11,3190.54 2139.14,3191.7 923.5,3193.15 5196.54,3199.1 1049.12,3201.15 4990.55,3201.69 5130.4,3203.77 4181.41,3206.12 2008.99,3207.71 4093.01,3216.2 668.99,3217.39 4924.59,3219.21 1120.91,3222.64 747.94,3223.58 579.01,3226.76 4843.93,3236.21 4731.49,3236.92 877.12,3239.53 1623.05,3241.1 1002.74,3247.53 3651.12,3250.27 4227.79,3252.5 4141.92,3259.9 5097.03,3260.24 5180,3262.57 4990.55,3267.28 1074.53,3269.02 3374.82,3271.85 3423.54,3277.41 668.99,3282.98 4777.87,3283.3 4924.59,3284.8 830.74,3285.91 747.94,3289.17 580.91,3292.32 1581.41,3291.77 956.36,3293.91 4274.17,3298.88 2299.9,3306.54 4188.3,3306.28 5050.65,3306.62 5137.78,3312.77 1028.15,3315.4 1644.06,3322.41 3429.1,3326.13 1535.03,3338.15 2399.43,3343.42 4320.55,3345.26 606.72,3352.62 4234.67,3352.66 5091.4,3359.15 981.77,3361.78 1597.68,3368.79 1018.81,3370.45 1084.4,3370.45 1149.99,3370.45 1215.58,3370.45 1281.17,3370.45 1346.76,3370.45 1412.35,3370.45 1477.94,3370.45 3337.93,3371.37 4366.93,3391.64 2393.86,3392.14 3966.15,3396.23 2345.14,3397.71 4281.05,3399.04 2215,3413.72 5054.37,3413.28 4428.11,3415.28 4493.7,3415.28 4559.29,3415.28 4624.88,3415.28 4327.71,3445.15 3905.9,3446.56 4009.09,3445.81 958.3,3451.11 1023.89,3451.11 1089.48,3451.11 1155.07,3451.11 1220.66,3451.11 1286.25,3451.11 1351.84,3451.11 1417.43,3451.11 1483.02,3451.11 1548.61,3451.11 1614.2,3451.11 1679.8,3451.11 1745.39,3451.11 1810.98,3451.11 3445.11,3456.28 5009.82,3457.82 4385.26,3476.61 4450.69,3481.24 4516.28,3481.24 4581.87,3481.24 4647.46,3481.24 4713.05,3481.24 4778.64,3481.83 3957.3,3487.3 4058.56,3488.88 4123.93,3494.24 4189.52,3494.24 4255.11,3494.24 701.83,3503.93 1012.54,3517.07 1078.13,3517.07 1143.72,3517.07 1209.31,3517.07 1274.9,3517.07 1340.49,3517.07 1406.08,3517.07 1471.67,3517.07 1537.26,3517.07 1602.85,3517.07 1668.44,3517.07 1734.04,3517.07 1799.63,3517.07 1865.06,3521.65 4977.42,3527.36 898.41,3530.81 4004.68,3532.66 4065.03,3558.35 4130.59,3560.2 4196.18,3560.2 4261.77,3560.2 4327.36,3560.2 4392.95,3560.2 4458.55,3560.2 4524.14,3560.2 4589.73,3560.2 4655.32,3560.2 4720.91,3560.2 4786.5,3560.2 3746.77,3584.22 3812.36,3584.22 3877.95,3584.22 3943.54,3584.22 932.34,3586.94 4837.14,3613.08 978.72,3633.32 895.41,3643.29 4779.94,3645.17 3796.27,3650.18 3861.86,3650.18 3927.45,3650.18 3993.04,3650.18 4058.64,3650.18 4124.23,3650.18 4189.82,3650.18 4255.41,3650.18 4321,3650.18 4386.59,3650.18 4452.18,3650.18 4517.77,3650.18 4583.36,3650.18 4648.95,3650.18 4714.54,3650.18 1039.84,3657.12 1105.43,3657.12 1171.02,3657.12 1236.61,3657.12 1302.2,3657.12 1367.79,3657.12 1433.38,3657.12 1498.97,3657.12 1564.56,3657.12 1630.15,3657.12 1695.74,3657.12 1761.34,3657.12 1826.93,3657.12 1892.52,3657.12 1958.11,3657.12 2023.7,3657.12 3731.14,3657.93 942.25,3689.2 1000.55,3719.25 1066.03,3723.08 1131.62,3723.08 1197.21,3723.08 1262.8,3723.08 1328.39,3723.08 1393.98,3723.08 1459.57,3723.08 1525.16,3723.08 1590.75,3723.08 1656.34,3723.08 1721.93,3723.08 1787.53,3723.08 1853.12,3723.08 1918.71,3723.08 1984.3,3723.08 2064.79,3730.51
  other v3: 2792.38,-1259.84 2851.43,-1259.84 2910.49,-1259.84 2467.57,-1230.31 2536.47,-1230.31 2605.37,-1230.31 3097.5,-1230.31 3166.39,-1230.31 3235.29,-1230.31 2792.38,-1210.63 2910.49,-1210.63 3272.09,-1200.79 3323.87,-1200.79 3382.93,-1200.79 3441.56,-1200.79 3500.53,-1200.79 2211.67,-1191.93 2260.88,-1191.93 2319.94,-1191.93 2378.99,-1191.93 2430.48,-1191.93 3097.5,-1156.5 3235.29,-1156.5 3272.09,-1156.5 3382.93,-1156.5 3500.36,-1156.5 2211.67,-1154.53 2319.94,-1154.53 2430.48,-1154.53 2467.57,-1154.53 2605.37,-1154.53 2792.38,-1154.53 2910.49,-1154.53 272.69,728.86 316.98,729.02 5383.91,738.19 5421.32,738.19 5421.32,787.4 272.69,787.83 272.69,846.46 316.98,846.46 5383.91,846.46 5421.32,846.46 272.69,905.51 5421.32,905.51 272.69,957.3 316.98,957.3 5383.91,957 5421.32,957 243.17,994.09 316.98,994.09 5383.91,994.09 5459.7,994.09 243.17,1062.99 5459.7,1062.99 243.17,1131.89 316.98,1131.89 5383.91,1131.89 5459.7,1131.89 213.64,1318.9 262.85,1318.9 318.95,1318.9 5383.91,1318.9 5440.02,1318.9 5489.23,1318.9 213.64,1377.95 5489.23,1377.95 213.64,1437.01 262.85,1437.01 318.95,1437.01 5383.91,1437.01 5440.02,1437.01 5489.23,1437.01 243.17,1624.02 318.95,1624.02 5385.88,1624.02 5459.7,1624.02 243.17,1692.91 5459.7,1692.91 243.17,1761.81 318.95,1761.81 5385.88,1761.81 5459.7,1761.81 5385.88,1798.61 5430.17,1798.61 281.55,1798.9 318.95,1798.9 281.55,1850.39 5430.17,1850.39 281.55,1909.45 318.95,1909.45 5385.88,1909.45 5430.17,1909.45 281.55,1968.5 5430.17,1968.07 281.55,2017.72 318.95,2017.72 5385.88,2026.88 5430.17,2027.05 2792.38,3910.43 2910.49,3910.43 3097.5,3910.43 3235.29,3910.43 3272.38,3910.43 3382.93,3910.43 3491.2,3910.43 2202.5,3912.4 2319.94,3912.4 2430.78,3912.4 2467.57,3912.4 2605.37,3912.4 3272.38,3947.83 3323.87,3947.83 3382.93,3947.83 3441.98,3947.83 3491.2,3947.83 2202.34,3956.69 2261.31,3956.69 2319.94,3956.69 2378.99,3956.69 2430.78,3956.69 2792.38,3966.54 2910.49,3966.54 2467.57,3986.22 2536.47,3986.22 2605.37,3986.22 3097.5,3986.22 3166.39,3986.22 3235.29,3986.22 2792.38,4015.75 2851.43,4015.75 2910.49,4015.75
  other v5: 5090.55,-901.57 555.12,-874.02 5137.8,3622.05 613.65,3657.48
NetA1_C13_1: A1_C13.1 A1_L1.1 A1_RF1.1 | length 153
  Top Layer - SIG1 w20: A1_C13.1@1253.45,58.29 A1_L1.1@1303.56,108.4 ; A1_L1.1@1303.81,108.4 A1_RF1.1@1361.87,166.46
NetA1_C13_2: A1_C13.2 A1_L2.1 | length 51.2
  Top Layer - SIG1 w20: A1_L2.1@1188.03,-7.13 A1_C13.2@1224.22,29.06
NetA1_Cin_1_2: A1_Cin_1.2 A1_RF1.3 | length 58.1
  Top Layer - SIG1 w20: A1_RF1.3@1459.45,191.92 A1_Cin_1.2@1500.52,232.98
NetA2_C13_1: A2_C13.1 A2_L1.1 A2_RF1.1 | length 153
  Top Layer - SIG1 w20: A2_C13.1@1047.8,263.94 A2_L1.1@1097.91,314.05 ; A2_L1.1@1098.16,314.05 A2_RF1.1@1156.22,372.11
NetA2_C13_2: A2_C13.2 A2_L2.1 | length 51.2
  Top Layer - SIG1 w20: A2_L2.1@982.37,198.52 A2_C13.2@1018.56,234.71
NetA2_Cin_1_2: A2_Cin_1.2 A2_RF1.3 | length 58.1
  Top Layer - SIG1 w20: A2_RF1.3@1253.8,397.57 A2_Cin_1.2@1294.87,438.63
NetA3_C13_1: A3_C13.1 A3_L1.1 A3_RF1.1 | length 153
  Top Layer - SIG1 w20: A3_C13.1@841.79,469.95 A3_L1.1@891.9,520.06 ; A3_L1.1@892.15,520.06 A3_RF1.1@950.21,578.12
NetA3_C13_2: A3_C13.2 A3_L2.1 | length 51.2
  Top Layer - SIG1 w20: A3_L2.1@776.37,404.53 A3_C13.2@812.56,440.72
NetA3_Cin_1_2: A3_Cin_1.2 A3_RF1.3 | length 58.1
  Top Layer - SIG1 w20: A3_RF1.3@1047.8,603.58 A3_Cin_1.2@1088.86,644.64
NetA4_C13_1: A4_C13.1 A4_L1.1 A4_RF1.1 | length 153
  Top Layer - SIG1 w20: A4_C13.1@635.78,675.96 A4_L1.1@685.89,726.07 ; A4_L1.1@686.15,726.07 A4_RF1.1@744.21,784.13
NetA4_C13_2: A4_C13.2 A4_L2.1 | length 51.2
  Top Layer - SIG1 w20: A4_L2.1@570.36,610.54 A4_C13.2@606.55,646.73
NetA4_Cin_1_2: A4_Cin_1.2 A4_RF1.3 | length 58.1
  Top Layer - SIG1 w20: A4_RF1.3@841.79,809.59 A4_Cin_1.2@882.85,850.65
NetA5_C13_1: A5_C13.1 A5_L1.1 A5_RF1.1 | length 153
  Top Layer - SIG1 w20: A5_C13.1@707.71,2151.97 A5_L1.1@757.82,2101.86 ; A5_L1.1@757.82,2101.6 A5_RF1.1@815.88,2043.54
NetA5_C13_2: A5_C13.2 A5_L2.1 | length 51.2
  Top Layer - SIG1 w20: A5_L2.1@642.29,2217.39 A5_C13.2@678.48,2181.2
NetA5_Cin_1_2: A5_Cin_1.2 A5_RF1.3 | length 58.1
  Top Layer - SIG1 w20: A5_RF1.3@841.34,1945.96 A5_Cin_1.2@882.4,1904.9
NetA6_C13_1: A6_C13.1 A6_L1.1 A6_RF1.1 | length 153
  Top Layer - SIG1 w20: A6_C13.1@913.72,2357.98 A6_L1.1@963.83,2307.87 ; A6_L1.1@963.83,2307.61 A6_RF1.1@1021.89,2249.55
NetA6_C13_2: A6_C13.2 A6_L2.1 | length 51.2
  Top Layer - SIG1 w20: A6_L2.1@848.3,2423.4 A6_C13.2@884.49,2387.21
NetA6_Cin_1_2: A6_Cin_1.2 A6_RF1.3 | length 58.1
  Top Layer - SIG1 w20: A6_RF1.3@1047.34,2151.97 A6_Cin_1.2@1088.41,2110.91
NetA7_C13_1: A7_C13.1 A7_L1.1 A7_RF1.1 | length 153
  Top Layer - SIG1 w20: A7_C13.1@1119.73,2563.99 A7_L1.1@1169.84,2513.88 ; A7_L1.1@1169.84,2513.62 A7_RF1.1@1227.9,2455.56
NetA7_C13_2: A7_C13.2 A7_L2.1 | length 51.2
  Top Layer - SIG1 w20: A7_L2.1@1054.31,2629.41 A7_C13.2@1090.5,2593.22
NetA7_Cin_1_2: A7_Cin_1.2 A7_RF1.3 | length 58.1
  Top Layer - SIG1 w20: A7_RF1.3@1253.35,2357.98 A7_Cin_1.2@1294.42,2316.92
NetA8_C13_1: A8_C13.1 A8_L1.1 A8_RF1.1 | length 153
  Top Layer - SIG1 w20: A8_C13.1@1325.73,2769.99 A8_L1.1@1375.84,2719.88 ; A8_L1.1@1375.84,2719.63 A8_RF1.1@1433.9,2661.57
NetA8_C13_2: A8_C13.2 A8_L2.1 | length 51.2
  Top Layer - SIG1 w20: A8_L2.1@1260.31,2835.41 A8_C13.2@1296.5,2799.22
NetA8_Cin_1_2: A8_Cin_1.2 A8_RF1.3 | length 58.1
  Top Layer - SIG1 w20: A8_RF1.3@1459.36,2563.99 A8_Cin_1.2@1500.42,2522.92
NetA9_C13_1: A9_C13.1 A9_L1.1 A9_RF1.1 | length 153
  Bottom Layer - SIG4 w20: A9_C13.1@1253.35,2697.61 A9_L1.1@1303.46,2647.5 ; A9_L1.1@1303.72,2647.5 A9_RF1.1@1361.78,2589.44
NetA9_C13_2: A9_C13.2 A9_L2.1 | length 51.2
  Bottom Layer - SIG4 w20: A9_L2.1@1187.93,2763.03 A9_C13.2@1224.12,2726.84
NetA9_Cin_1_2: A9_Cin_1.2 A9_RF1.3 | length 58.1
  Bottom Layer - SIG4 w20: A9_RF1.3@1459.36,2563.99 A9_Cin_1.2@1500.42,2522.92
NetA10_C13_1: A10_C13.1 A10_L1.1 A10_RF1.1 | length 153
  Bottom Layer - SIG4 w20: A10_C13.1@1047.35,2491.6 A10_L1.1@1097.46,2441.49 ; A10_L1.1@1097.71,2441.49 A10_RF1.1@1155.77,2383.43
NetA10_C13_2: A10_C13.2 A10_L2.1 | length 51.2
  Bottom Layer - SIG4 w20: A10_L2.1@981.92,2557.03 A10_C13.2@1018.11,2520.84
NetA10_Cin_1_2: A10_Cin_1.2 A10_RF1.3 | length 58.1
  Bottom Layer - SIG4 w20: A10_RF1.3@1253.35,2357.98 A10_Cin_1.2@1294.42,2316.92
NetA11_C13_1: A11_C13.1 A11_L1.1 A11_RF1.1 | length 153
  Bottom Layer - SIG4 w20: A11_C13.1@841.34,2285.6 A11_L1.1@891.45,2235.49 ; A11_L1.1@891.7,2235.49 A11_RF1.1@949.76,2177.43
NetA11_C13_2: A11_C13.2 A11_L2.1 | length 51.2
  Bottom Layer - SIG4 w20: A11_L2.1@775.92,2351.02 A11_C13.2@812.11,2314.83
NetA11_Cin_1_2: A11_Cin_1.2 A11_RF1.3 | length 58.1
  Bottom Layer - SIG4 w20: A11_RF1.3@1047.35,2151.97 A11_Cin_1.2@1088.41,2110.91
NetA12_C13_1: A12_C13.1 A12_L1.1 A12_RF1.1 | length 153
  Bottom Layer - SIG4 w20: A12_C13.1@635.33,2079.59 A12_L1.1@685.44,2029.48 ; A12_L1.1@685.7,2029.48 A12_RF1.1@743.76,1971.42
NetA12_C13_2: A12_C13.2 A12_L2.1 | length 51.2
  Bottom Layer - SIG4 w20: A12_L2.1@569.91,2145.01 A12_C13.2@606.1,2108.82
NetA12_Cin_1_2: A12_Cin_1.2 A12_RF1.3 | length 58.1
  Bottom Layer - SIG4 w20: A12_RF1.3@841.34,1945.96 A12_Cin_1.2@882.4,1904.9
NetA13_C13_1: A13_C13.1 A13_L1.1 A13_RF1.1 | length 153
  Bottom Layer - SIG4 w20: A13_C13.1@708.16,603.58 A13_L1.1@758.27,653.69 ; A13_L1.1@758.27,653.94 A13_RF1.1@816.33,712.01
NetA13_C13_2: A13_C13.2 A13_L2.1 | length 51.2
  Bottom Layer - SIG4 w20: A13_L2.1@642.74,538.16 A13_C13.2@678.93,574.35
NetA13_Cin_1_2: A13_Cin_1.2 A13_RF1.3 | length 58.1
  Bottom Layer - SIG4 w20: A13_RF1.3@841.79,809.59 A13_Cin_1.2@882.85,850.65
NetA14_C13_1: A14_C13.1 A14_L1.1 A14_RF1.1 | length 153
  Bottom Layer - SIG4 w20: A14_C13.1@914.17,397.57 A14_L1.1@964.28,447.68 ; A14_L1.1@964.28,447.94 A14_RF1.1@1022.34,506
NetA14_C13_2: A14_C13.2 A14_L2.1 | length 51.2
  Bottom Layer - SIG4 w20: A14_L2.1@848.75,332.15 A14_C13.2@884.94,368.34
NetA14_Cin_1_2: A14_Cin_1.2 A14_RF1.3 | length 58.1
  Bottom Layer - SIG4 w20: A14_RF1.3@1047.8,603.58 A14_Cin_1.2@1088.86,644.64
NetA15_C13_1: A15_C13.1 A15_L1.1 A15_RF1.1 | length 153
  Bottom Layer - SIG4 w20: A15_C13.1@1120.18,191.56 A15_L1.1@1170.29,241.67 ; A15_L1.1@1170.29,241.93 A15_RF1.1@1228.35,299.99
NetA15_C13_2: A15_C13.2 A15_L2.1 | length 51.2
  Bottom Layer - SIG4 w20: A15_L2.1@1054.76,126.14 A15_C13.2@1090.95,162.33
NetA15_Cin_1_2: A15_Cin_1.2 A15_RF1.3 | length 58.1
  Bottom Layer - SIG4 w20: A15_RF1.3@1253.8,397.57 A15_Cin_1.2@1294.86,438.63
NetA16_C13_1: A16_C13.1 A16_L1.1 A16_RF1.1 | length 153
  Bottom Layer - SIG4 w20: A16_C13.1@1325.83,-14.09 A16_L1.1@1375.94,36.02 ; A16_L1.1@1375.94,36.28 A16_RF1.1@1434,94.34
NetA16_C13_2: A16_C13.2 A16_L2.1 | length 51.2
  Bottom Layer - SIG4 w20: A16_L2.1@1260.41,-79.51 A16_C13.2@1296.6,-43.32
NetA16_Cin_1_2: A16_Cin_1.2 A16_RF1.3 | length 58.1
  Bottom Layer - SIG4 w20: A16_RF1.3@1459.45,191.92 A16_Cin_1.2@1500.52,232.98
NetA17_C13_1: A17_C13.1 A17_L1.1 A17_RF1.1 | length 153
  Bottom Layer - SIG4 w20: A17_RF1.1@4062.92,2867.41 A17_L1.1@4120.98,2925.47 ; A17_L1.1@4120.98,2925.73 A17_C13.1@4171.09,2975.84
NetA17_C13_2: A17_C13.2 A17_L2.1 | length 51.2
  Bottom Layer - SIG4 w20: A17_C13.2@4200.32,3005.07 A17_L2.1@4236.51,3041.26
NetA17_Cin_1_2: A17_Cin_1.2 A17_RF1.3 | length 58.1
  Bottom Layer - SIG4 w20: A17_Cin_1.2@3996.4,2728.77 A17_RF1.3@4037.47,2769.83
NetA18_C13_1: A18_C13.1 A18_L1.1 A18_RF1.1 | length 153
  Bottom Layer - SIG4 w20: A18_RF1.1@3856.91,3073.42 A18_L1.1@3914.98,3131.48 ; A18_L1.1@3914.98,3131.73 A18_C13.1@3965.09,3181.84
NetA18_C13_2: A18_C13.2 A18_L2.1 | length 51.2
  Bottom Layer - SIG4 w20: A18_C13.2@3994.32,3211.07 A18_L2.1@4030.51,3247.26
NetA18_Cin_1_2: A18_Cin_1.2 A18_RF1.3 | length 58.1
  Bottom Layer - SIG4 w20: A18_Cin_1.2@3790.4,2934.77 A18_RF1.3@3831.46,2975.84
NetA19_C13_1: A19_C13.1 A19_L1.1 A19_RF1.1 | length 153
  Bottom Layer - SIG4 w20: A19_RF1.1@3650.91,3279.42 A19_L1.1@3708.97,3337.48 ; A19_L1.1@3708.97,3337.74 A19_C13.1@3759.08,3387.85
NetA19_C13_2: A19_C13.2 A19_L2.1 | length 51.2
  Bottom Layer - SIG4 w20: A19_C13.2@3788.31,3417.08 A19_L2.1@3824.5,3453.27
NetA19_Cin_1_2: A19_Cin_1.2 A19_RF1.3 | length 58.1
  Bottom Layer - SIG4 w20: A19_Cin_1.2@3584.39,3140.78 A19_RF1.3@3625.45,3181.84
NetA20_C13_1: A20_C13.1 A20_L1.1 A20_RF1.1 | length 153
  Bottom Layer - SIG4 w20: A20_RF1.1@3444.9,3485.43 A20_L1.1@3502.96,3543.49 ; A20_L1.1@3502.96,3543.75 A20_C13.1@3553.07,3593.86
NetA20_C13_2: A20_C13.2 A20_L2.1 | length 51.2
  Bottom Layer - SIG4 w20: A20_C13.2@3582.3,3623.09 A20_L2.1@3618.49,3659.28
NetA20_Cin_1_2: A20_Cin_1.2 A20_RF1.3 | length 58.1
  Bottom Layer - SIG4 w20: A20_Cin_1.2@3378.38,3346.79 A20_RF1.3@3419.44,3387.85
NetA21_C13_1: A21_C13.1 A21_L1.1 A21_RF1.1 | length 153
  Bottom Layer - SIG4 w20: A21_C13.1@2077.42,3521.68 A21_L1.1@2127.53,3471.57 ; A21_L1.1@2127.78,3471.57 A21_RF1.1@2185.84,3413.5
NetA21_C13_2: A21_C13.2 A21_L2.1 | length 51.2
  Bottom Layer - SIG4 w20: A21_L2.1@2012,3587.1 A21_C13.2@2048.19,3550.91
NetA21_Cin_1_2: A21_Cin_1.2 A21_RF1.3 | length 58.1
  Bottom Layer - SIG4 w20: A21_RF1.3@2283.42,3388.05 A21_Cin_1.2@2324.49,3346.99
NetA22_C13_1: A22_C13.1 A22_L1.1 A22_RF1.1 | length 153
  Bottom Layer - SIG4 w20: A22_C13.1@1871.41,3315.67 A22_L1.1@1921.52,3265.56 ; A22_L1.1@1921.78,3265.56 A22_RF1.1@1979.84,3207.5
NetA22_C13_2: A22_C13.2 A22_L2.1 | length 51.2
  Bottom Layer - SIG4 w20: A22_L2.1@1805.99,3381.09 A22_C13.2@1842.18,3344.9
NetA22_Cin_1_2: A22_Cin_1.2 A22_RF1.3 | length 58.1
  Bottom Layer - SIG4 w20: A22_RF1.3@2077.42,3182.04 A22_Cin_1.2@2118.48,3140.98
NetA23_C13_1: A23_C13.1 A23_L1.1 A23_RF1.1 | length 153
  Bottom Layer - SIG4 w20: A23_C13.1@1665.4,3109.66 A23_L1.1@1715.51,3059.55 ; A23_L1.1@1715.77,3059.55 A23_RF1.1@1773.83,3001.49
NetA23_C13_2: A23_C13.2 A23_L2.1 | length 51.2
  Bottom Layer - SIG4 w20: A23_L2.1@1599.98,3175.08 A23_C13.2@1636.17,3138.89
NetA23_Cin_1_2: A23_Cin_1.2 A23_RF1.3 | length 58.1
  Bottom Layer - SIG4 w20: A23_RF1.3@1871.41,2976.03 A23_Cin_1.2@1912.47,2934.97
NetA24_C13_1: A24_C13.1 A24_L1.1 A24_RF1.1 | length 153
  Bottom Layer - SIG4 w20: A24_C13.1@1459.39,2903.65 A24_L1.1@1509.5,2853.54 ; A24_L1.1@1509.76,2853.54 A24_RF1.1@1567.82,2795.48
NetA24_C13_2: A24_C13.2 A24_L2.1 | length 51.2
  Bottom Layer - SIG4 w20: A24_L2.1@1393.97,2969.07 A24_C13.2@1430.16,2932.88
NetA24_Cin_1_2: A24_Cin_1.2 A24_RF1.3 | length 58.1
  Bottom Layer - SIG4 w20: A24_RF1.3@1665.4,2770.03 A24_Cin_1.2@1706.46,2728.96
NetA25_C13_1: A25_C13.1 A25_L1.1 A25_RF1.1 | length 153
  Top Layer - SIG1 w20: A25_C13.1@1531.77,2976.03 A25_L1.1@1581.88,2925.92 ; A25_L1.1@1581.88,2925.67 A25_RF1.1@1639.95,2867.61
NetA25_C13_2: A25_C13.2 A25_L2.1 | length 51.2
  Top Layer - SIG1 w20: A25_L2.1@1466.35,3041.45 A25_C13.2@1502.54,3005.26
NetA25_Cin_1_2: A25_Cin_1.2 A25_RF1.3 | length 58.1
  Top Layer - SIG1 w20: A25_RF1.3@1665.4,2770.03 A25_Cin_1.2@1706.46,2728.96
NetA26_C13_1: A26_C13.1 A26_L1.1 A26_RF1.1 | length 153
  Top Layer - SIG1 w20: A26_C13.1@1737.78,3182.04 A26_L1.1@1787.89,3131.93 ; A26_L1.1@1787.89,3131.68 A26_RF1.1@1845.95,3073.61
NetA26_C13_2: A26_C13.2 A26_L2.1 | length 51.2
  Top Layer - SIG1 w20: A26_L2.1@1672.36,3247.46 A26_C13.2@1708.55,3211.27
NetA26_Cin_1_2: A26_Cin_1.2 A26_RF1.3 | length 58.1
  Top Layer - SIG1 w20: A26_RF1.3@1871.41,2976.03 A26_Cin_1.2@1912.47,2934.97
NetA27_C13_1: A27_C13.1 A27_L1.1 A27_RF1.1 | length 153
  Top Layer - SIG1 w20: A27_C13.1@1943.79,3388.05 A27_L1.1@1993.9,3337.94 ; A27_L1.1@1993.9,3337.68 A27_RF1.1@2051.96,3279.62
NetA27_C13_2: A27_C13.2 A27_L2.1 | length 51.2
  Top Layer - SIG1 w20: A27_L2.1@1878.37,3453.47 A27_C13.2@1914.56,3417.28
NetA27_Cin_1_2: A27_Cin_1.2 A27_RF1.3 | length 58.1
  Top Layer - SIG1 w20: A27_RF1.3@2077.42,3182.04 A27_Cin_1.2@2118.48,3140.98
NetA28_C13_1: A28_C13.1 A28_L1.1 A28_RF1.1 | length 153
  Top Layer - SIG1 w20: A28_C13.1@2149.8,3594.06 A28_L1.1@2199.91,3543.95 ; A28_L1.1@2199.91,3543.69 A28_RF1.1@2257.97,3485.63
